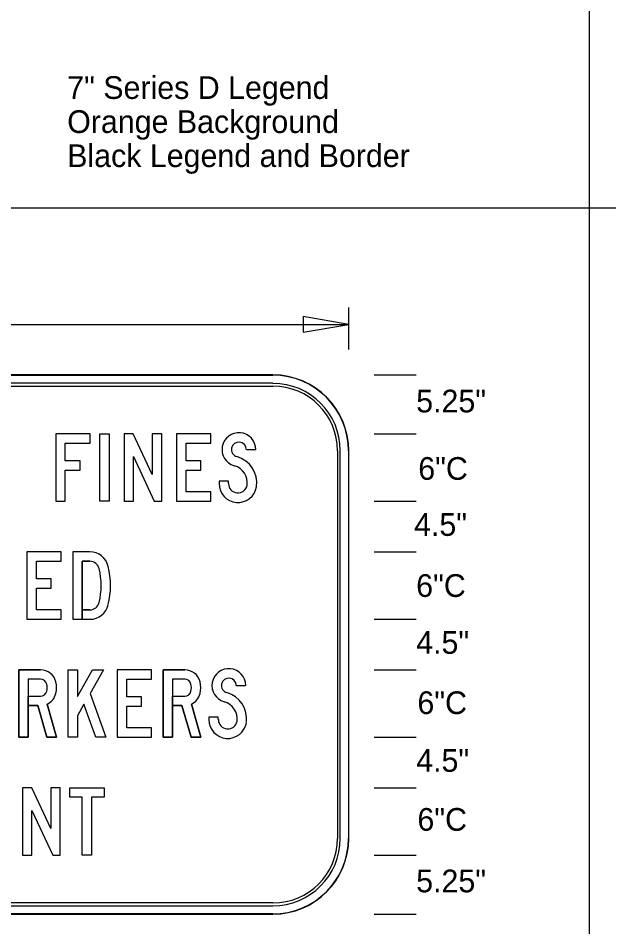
# Model space of a CAD drawing. Extents: x 0 to 770, y 0 to 495.
# Drawn here: x 296.9 to 388, y 219.2 to 359.3 of the extents above; entities that cross this region are included whole.
import ezdxf

# ---------------------------------------------------------------- set-up
doc = ezdxf.new("R2010")
doc.units = 0
for name, color, linetype in [('Dimension', 7, 'Continuous'), ('GSBWFill', 7, 'Continuous'), ('GSColorFill', 7, 'Continuous'), ('GSDims', 7, 'Continuous'), ('GSOutline', 7, 'Continuous'), ('SheetLines_dp', 7, 'Continuous'), ('TextStructures', 7, 'Continuous')]:
    doc.layers.add(name, color=color, linetype=linetype)

msp = doc.modelspace()

# ---------------------------------------------------------------- linework, layer by layer
at = {"layer": 'Dimension'}
msp.add_lwpolyline([(347.88, 312.06), (340.87, 313.25), (340.87, 310.87)], close=True, dxfattribs=at)
at = {"layer": 'GSBWFill'}
for p, q in [((336.19, 304.27), (234.87, 304.27)), ((336.19, 302.97), (234.87, 302.97)), ((234.87, 302.53), (336.19, 302.53)), ((332.09, 292.76), (333.54, 292.76)), ((346.15, 292.57), (346.15, 232.82)), ((346.58, 232.82), (346.58, 292.57)), ((347.88, 232.82), (347.88, 292.57)), ((329.33, 287.51), (329.33, 287.9)), ((307.97, 268.05), (306.78, 268.05)), ((330.53, 256.38), (331.98, 256.38)), ((300.35, 254.75), (300.35, 254.75)), ((322.59, 254.75), (322.59, 254.75)), ((327.77, 251.13), (327.77, 251.52)), ((336.19, 222.86), (234.87, 222.86)), ((234.87, 222.43), (336.19, 222.43)), ((234.87, 221.13), (336.19, 221.13))]:
    msp.add_line(p, q, dxfattribs=at)
for points in [[(304.18, 289.56), (306.46, 289.56), (306.46, 291.02), (304.18, 291.02), (304.18, 293.72), (308.03, 293.72), (308.03, 295.17), (302.73, 295.17), (302.73, 284.78), (304.18, 284.78)], [(309.48, 295.17), (310.94, 295.17), (310.94, 284.78), (309.48, 284.78)], [(317.9, 284.78), (319.04, 284.78), (319.04, 295.17), (317.59, 295.17), (317.59, 288.89), (314.66, 295.17), (313.23, 295.17), (313.23, 284.78), (314.68, 284.78), (314.68, 291.69)], [(322.79, 286.23), (322.79, 289.56), (325.06, 289.56), (325.06, 291.02), (322.79, 291.02), (322.79, 293.72), (326.63, 293.72), (326.63, 295.17), (321.33, 295.17), (321.33, 284.78), (326.63, 284.78), (326.63, 286.23)], [(299.72, 268.05), (299.72, 271.37), (301.99, 271.37), (301.99, 272.83), (299.72, 272.83), (299.72, 275.53), (303.56, 275.53), (303.56, 276.99), (298.26, 276.99), (298.26, 266.59), (303.56, 266.59), (303.56, 268.05)], [(307.05, 253.49), (306.05, 251.73), (306.05, 248.41), (304.6, 248.41), (304.6, 258.8), (306.05, 258.8), (306.05, 254.69), (308.38, 258.8), (310.06, 258.8), (308, 255.16), (310.42, 248.41), (308.87, 248.41)], [(313.64, 249.86), (313.64, 253.19), (315.92, 253.19), (315.92, 254.64), (313.64, 254.64), (313.64, 257.34), (317.49, 257.34), (317.49, 258.8), (312.19, 258.8), (312.19, 248.41), (317.49, 248.41), (317.49, 249.86)], [(302.26, 230.22), (303.4, 230.22), (303.4, 240.61), (301.95, 240.61), (301.95, 234.33), (299.02, 240.61), (297.58, 240.61), (297.58, 230.22), (299.04, 230.22), (299.04, 237.13)], [(306.78, 239.16), (304.86, 239.16), (304.86, 240.61), (310.16, 240.61), (310.16, 239.16), (308.24, 239.16), (308.24, 230.22), (306.78, 230.22)]]:
    msp.add_lwpolyline(points, close=True, dxfattribs=at)
for points in [[(329.33, 287.9), (327.88, 287.9), (327.88, 287.51)], [(307.97, 276.99), (305.33, 276.99), (305.33, 266.59), (306.78, 266.59), (306.78, 275.53), (307.97, 275.53)], [(306.78, 268.05), (306.78, 266.59), (307.97, 266.59)], [(300.35, 257.34), (298.47, 257.34), (298.47, 248.41), (297.01, 248.41), (297.01, 258.8), (300.35, 258.8)], [(322.59, 257.34), (320.71, 257.34), (320.71, 248.41), (319.25, 248.41), (319.25, 258.8), (322.59, 258.8)], [(301.38, 253.52), (302.83, 248.41), (301.32, 248.41), (299.93, 253.29), (298.47, 253.29), (298.47, 254.75), (300.35, 254.75)], [(323.62, 253.52), (325.07, 248.41), (323.56, 248.41), (322.17, 253.29), (320.71, 253.29), (320.71, 254.75), (322.59, 254.75)], [(327.77, 251.52), (326.32, 251.52), (326.32, 251.13)]]:
    msp.add_lwpolyline(points, dxfattribs=at)
for centre, radius, start, end in [((336.19, 292.57), 11.69, 0, 90), ((336.19, 292.57), 10.39, 0, 90), ((336.19, 292.57), 9.96, 0, 90), ((330.94, 292.76), 2.6, 0, 254.2259), ((330.94, 292.76), 1.14, 0, 254.2259), ((329.49, 287.61), 4.21, 352.1298, 74.2259), ((329.49, 287.61), 2.75, 352.5804, 74.2259), ((330.79, 287.51), 2.91, 180, 350.5313), ((330.79, 287.51), 1.45, 180, 349.7857), ((307.97, 274.08), 2.91, 13.109, 90), ((307.97, 274.08), 1.45, 13.109, 90), ((298.16, 271.79), 12.99, 346.891, 13.109), ((298.16, 271.79), 11.54, 346.891, 13.109), ((307.97, 269.5), 1.45, 270, 346.891), ((307.97, 269.5), 2.91, 270, 346.891), ((300.35, 256.36), 2.44, 13.8865, 90), ((322.59, 256.36), 2.44, 13.8865, 90), ((329.39, 256.38), 2.6, 0, 254.2259), ((300.35, 256.36), 0.987, 13.8865, 90), ((299.09, 256.04), 2.29, 346.1135, 13.8865), ((299.09, 256.04), 3.74, 346.1135, 13.8865), ((322.59, 256.36), 0.987, 13.8865, 90), ((321.33, 256.04), 2.29, 346.1135, 13.8865), ((321.33, 256.04), 3.74, 346.1135, 13.8865), ((329.39, 256.38), 1.14, 0, 254.2259), ((300.35, 255.73), 0.987, 270, 346.1135), ((300.35, 255.73), 2.44, 294.8221, 346.1135), ((322.59, 255.73), 0.987, 270, 346.1135), ((322.59, 255.73), 2.44, 294.8221, 346.1135), ((327.93, 251.23), 4.21, 352.1298, 74.2259), ((327.93, 251.23), 2.75, 352.5804, 74.2259), ((329.23, 251.13), 2.91, 180, 350.5313), ((329.23, 251.13), 1.45, 180, 349.7857), ((336.19, 232.82), 10.39, 270, 0), ((336.19, 232.82), 9.96, 270, 0), ((336.19, 232.82), 11.69, 270, 0)]:
    msp.add_arc(centre, radius, start, end, dxfattribs=at)
at = {"layer": 'GSColorFill'}
for p, q in [((336.19, 304.27), (234.87, 304.27)), ((234.87, 304.22), (336.19, 304.22)), ((336.19, 302.97), (234.87, 302.97)), ((234.87, 302.53), (336.19, 302.53)), ((332.09, 292.76), (333.54, 292.76)), ((346.15, 292.57), (346.15, 232.82)), ((346.58, 232.82), (346.58, 292.57)), ((347.84, 292.57), (347.84, 232.82)), ((347.88, 232.82), (347.88, 292.57)), ((329.33, 287.51), (329.33, 287.9)), ((307.97, 268.05), (306.78, 268.05)), ((330.53, 256.38), (331.98, 256.38)), ((300.35, 254.75), (300.35, 254.75)), ((322.59, 254.75), (322.59, 254.75)), ((327.77, 251.13), (327.77, 251.52)), ((336.19, 222.86), (234.87, 222.86)), ((234.87, 222.43), (336.19, 222.43)), ((336.19, 221.17), (234.87, 221.17)), ((234.87, 221.13), (336.19, 221.13))]:
    msp.add_line(p, q, dxfattribs=at)
for points in [[(304.18, 289.56), (306.46, 289.56), (306.46, 291.02), (304.18, 291.02), (304.18, 293.72), (308.03, 293.72), (308.03, 295.17), (302.73, 295.17), (302.73, 284.78), (304.18, 284.78)], [(309.48, 295.17), (310.94, 295.17), (310.94, 284.78), (309.48, 284.78)], [(317.9, 284.78), (319.04, 284.78), (319.04, 295.17), (317.59, 295.17), (317.59, 288.89), (314.66, 295.17), (313.23, 295.17), (313.23, 284.78), (314.68, 284.78), (314.68, 291.69)], [(322.79, 286.23), (322.79, 289.56), (325.06, 289.56), (325.06, 291.02), (322.79, 291.02), (322.79, 293.72), (326.63, 293.72), (326.63, 295.17), (321.33, 295.17), (321.33, 284.78), (326.63, 284.78), (326.63, 286.23)], [(299.72, 268.05), (299.72, 271.37), (301.99, 271.37), (301.99, 272.83), (299.72, 272.83), (299.72, 275.53), (303.56, 275.53), (303.56, 276.99), (298.26, 276.99), (298.26, 266.59), (303.56, 266.59), (303.56, 268.05)], [(307.05, 253.49), (306.05, 251.73), (306.05, 248.41), (304.6, 248.41), (304.6, 258.8), (306.05, 258.8), (306.05, 254.69), (308.38, 258.8), (310.06, 258.8), (308, 255.16), (310.42, 248.41), (308.87, 248.41)], [(313.64, 249.86), (313.64, 253.19), (315.92, 253.19), (315.92, 254.64), (313.64, 254.64), (313.64, 257.34), (317.49, 257.34), (317.49, 258.8), (312.19, 258.8), (312.19, 248.41), (317.49, 248.41), (317.49, 249.86)], [(302.26, 230.22), (303.4, 230.22), (303.4, 240.61), (301.95, 240.61), (301.95, 234.33), (299.02, 240.61), (297.58, 240.61), (297.58, 230.22), (299.04, 230.22), (299.04, 237.13)], [(306.78, 239.16), (304.86, 239.16), (304.86, 240.61), (310.16, 240.61), (310.16, 239.16), (308.24, 239.16), (308.24, 230.22), (306.78, 230.22)]]:
    msp.add_lwpolyline(points, close=True, dxfattribs=at)
for points in [[(329.33, 287.9), (327.88, 287.9), (327.88, 287.51)], [(307.97, 276.99), (305.33, 276.99), (305.33, 266.59), (306.78, 266.59), (306.78, 275.53), (307.97, 275.53)], [(306.78, 268.05), (306.78, 266.59), (307.97, 266.59)], [(300.35, 257.34), (298.47, 257.34), (298.47, 248.41), (297.01, 248.41), (297.01, 258.8), (300.35, 258.8)], [(322.59, 257.34), (320.71, 257.34), (320.71, 248.41), (319.25, 248.41), (319.25, 258.8), (322.59, 258.8)], [(301.38, 253.52), (302.83, 248.41), (301.32, 248.41), (299.93, 253.29), (298.47, 253.29), (298.47, 254.75), (300.35, 254.75)], [(323.62, 253.52), (325.07, 248.41), (323.56, 248.41), (322.17, 253.29), (320.71, 253.29), (320.71, 254.75), (322.59, 254.75)], [(327.77, 251.52), (326.32, 251.52), (326.32, 251.13)]]:
    msp.add_lwpolyline(points, dxfattribs=at)
for centre, radius, start, end in [((336.19, 292.57), 11.69, 0, 90), ((336.19, 292.57), 11.65, 0, 90), ((336.19, 292.57), 10.39, 0, 90), ((336.19, 292.57), 9.96, 0, 90), ((330.94, 292.76), 2.6, 0, 254.2259), ((330.94, 292.76), 1.14, 0, 254.2259), ((329.49, 287.61), 4.21, 352.1298, 74.2259), ((329.49, 287.61), 2.75, 352.5804, 74.2259), ((330.79, 287.51), 2.91, 180, 350.5313), ((330.79, 287.51), 1.45, 180, 349.7857), ((307.97, 274.08), 2.91, 13.109, 90), ((307.97, 274.08), 1.45, 13.109, 90), ((298.16, 271.79), 12.99, 346.891, 13.109), ((298.16, 271.79), 11.54, 346.891, 13.109), ((307.97, 269.5), 1.45, 270, 346.891), ((307.97, 269.5), 2.91, 270, 346.891), ((300.35, 256.36), 2.44, 13.8865, 90), ((322.59, 256.36), 2.44, 13.8865, 90), ((329.39, 256.38), 2.6, 0, 254.2259), ((300.35, 256.36), 0.987, 13.8865, 90), ((299.09, 256.04), 2.29, 346.1135, 13.8865), ((299.09, 256.04), 3.74, 346.1135, 13.8865), ((322.59, 256.36), 0.987, 13.8865, 90), ((321.33, 256.04), 2.29, 346.1135, 13.8865), ((321.33, 256.04), 3.74, 346.1135, 13.8865), ((329.39, 256.38), 1.14, 0, 254.2259), ((300.35, 255.73), 0.987, 270, 346.1135), ((300.35, 255.73), 2.44, 294.8221, 346.1135), ((322.59, 255.73), 0.987, 270, 346.1135), ((322.59, 255.73), 2.44, 294.8221, 346.1135), ((327.93, 251.23), 4.21, 352.1298, 74.2259), ((327.93, 251.23), 2.75, 352.5804, 74.2259), ((329.23, 251.13), 2.91, 180, 350.5313), ((329.23, 251.13), 1.45, 180, 349.7857), ((336.19, 232.82), 10.39, 270, 0), ((336.19, 232.82), 9.96, 270, 0), ((336.19, 232.82), 11.69, 270, 0), ((336.19, 232.82), 11.65, 270, 0)]:
    msp.add_arc(centre, radius, start, end, dxfattribs=at)
at = {"layer": 'GSDims'}
for p, q in [((347.88, 308.16), (347.88, 314.66)), ((223.18, 312.06), (347.88, 312.06)), ((351.78, 304.27), (358.28, 304.27)), ((351.78, 295.17), (358.28, 295.17)), ((351.78, 295.17), (358.28, 295.17)), ((351.78, 284.78), (358.28, 284.78)), ((351.78, 284.78), (358.28, 284.78)), ((351.78, 276.99), (358.28, 276.99)), ((351.78, 276.99), (358.28, 276.99)), ((351.78, 266.59), (358.28, 266.59)), ((351.78, 266.59), (358.28, 266.59)), ((351.78, 258.8), (358.28, 258.8)), ((351.78, 258.8), (358.28, 258.8)), ((351.78, 248.41), (358.28, 248.41)), ((351.78, 248.41), (358.28, 248.41)), ((351.78, 240.61), (358.28, 240.61)), ((351.78, 240.61), (358.28, 240.61)), ((351.78, 230.22), (358.28, 230.22)), ((351.78, 230.22), (358.28, 230.22)), ((351.78, 221.13), (358.28, 221.13))]:
    msp.add_line(p, q, dxfattribs=at)
at = {"layer": 'GSOutline'}
for p, q in [((332.09, 292.76), (333.54, 292.76)), ((329.33, 287.51), (329.33, 287.9)), ((306.78, 268.05), (307.97, 268.05)), ((307.97, 266.59), (307.97, 266.59)), ((300.35, 258.8), (297.01, 258.8)), ((322.59, 258.8), (319.25, 258.8)), ((300.35, 257.34), (300.35, 257.34)), ((322.59, 257.34), (322.59, 257.34)), ((330.53, 256.38), (331.98, 256.38)), ((327.77, 251.13), (327.77, 251.52))]:
    msp.add_line(p, q, dxfattribs=at)
for points in [[(304.18, 289.56), (306.46, 289.56), (306.46, 291.02), (304.18, 291.02), (304.18, 293.72), (308.03, 293.72), (308.03, 295.17), (302.73, 295.17), (302.73, 284.78), (304.18, 284.78)], [(309.48, 295.17), (310.94, 295.17), (310.94, 284.78), (309.48, 284.78)], [(317.9, 284.78), (319.04, 284.78), (319.04, 295.17), (317.59, 295.17), (317.59, 288.89), (314.66, 295.17), (313.23, 295.17), (313.23, 284.78), (314.68, 284.78), (314.68, 291.69)], [(322.79, 286.23), (322.79, 289.56), (325.06, 289.56), (325.06, 291.02), (322.79, 291.02), (322.79, 293.72), (326.63, 293.72), (326.63, 295.17), (321.33, 295.17), (321.33, 284.78), (326.63, 284.78), (326.63, 286.23)], [(299.72, 268.05), (299.72, 271.37), (301.99, 271.37), (301.99, 272.83), (299.72, 272.83), (299.72, 275.53), (303.56, 275.53), (303.56, 276.99), (298.26, 276.99), (298.26, 266.59), (303.56, 266.59), (303.56, 268.05)], [(307.05, 253.49), (306.05, 251.73), (306.05, 248.41), (304.6, 248.41), (304.6, 258.8), (306.05, 258.8), (306.05, 254.69), (308.38, 258.8), (310.06, 258.8), (308, 255.16), (310.42, 248.41), (308.87, 248.41)], [(313.64, 249.86), (313.64, 253.19), (315.92, 253.19), (315.92, 254.64), (313.64, 254.64), (313.64, 257.34), (317.49, 257.34), (317.49, 258.8), (312.19, 258.8), (312.19, 248.41), (317.49, 248.41), (317.49, 249.86)], [(302.26, 230.22), (303.4, 230.22), (303.4, 240.61), (301.95, 240.61), (301.95, 234.33), (299.02, 240.61), (297.58, 240.61), (297.58, 230.22), (299.04, 230.22), (299.04, 237.13)], [(306.78, 239.16), (304.86, 239.16), (304.86, 240.61), (310.16, 240.61), (310.16, 239.16), (308.24, 239.16), (308.24, 230.22), (306.78, 230.22)]]:
    msp.add_lwpolyline(points, close=True, dxfattribs=at)
for points in [[(329.33, 287.9), (327.88, 287.9), (327.88, 287.51)], [(307.97, 276.99), (305.33, 276.99), (305.33, 266.59), (307.97, 266.59)], [(307.97, 275.53), (306.78, 275.53), (306.78, 268.05)], [(297.01, 258.8), (297.01, 248.41), (298.47, 248.41), (298.47, 253.29), (299.93, 253.29), (301.32, 248.41), (302.83, 248.41), (301.38, 253.52)], [(319.25, 258.8), (319.25, 248.41), (320.71, 248.41), (320.71, 253.29), (322.17, 253.29), (323.56, 248.41), (325.07, 248.41), (323.62, 253.52)], [(300.35, 257.34), (298.47, 257.34), (298.47, 254.75), (300.35, 254.75)], [(322.59, 257.34), (320.71, 257.34), (320.71, 254.75), (322.59, 254.75)], [(327.77, 251.52), (326.32, 251.52), (326.32, 251.13)]]:
    msp.add_lwpolyline(points, dxfattribs=at)
for centre, radius, start, end in [((330.94, 292.76), 2.6, 0, 254.2259), ((330.94, 292.76), 1.14, 0, 254.2259), ((329.49, 287.61), 4.21, 352.1298, 74.2259), ((329.49, 287.61), 2.75, 352.5804, 74.2259), ((330.79, 287.51), 2.91, 180, 350.5313), ((330.79, 287.51), 1.45, 180, 349.7857), ((307.97, 274.08), 2.91, 13.109, 90), ((307.97, 274.08), 1.45, 13.109, 90), ((298.16, 271.79), 12.99, 346.891, 13.109), ((298.16, 271.79), 11.54, 346.891, 13.109), ((307.97, 269.5), 1.45, 270, 346.891), ((307.97, 269.5), 2.91, 270, 346.891), ((300.35, 256.36), 2.44, 13.8865, 90), ((322.59, 256.36), 2.44, 13.8865, 90), ((329.39, 256.38), 2.6, 0, 254.2259), ((300.35, 256.36), 0.987, 13.8865, 90), ((299.09, 256.04), 2.29, 346.1135, 13.8865), ((299.09, 256.04), 3.74, 346.1135, 13.8865), ((322.59, 256.36), 0.987, 13.8865, 90), ((321.33, 256.04), 2.29, 346.1135, 13.8865), ((321.33, 256.04), 3.74, 346.1135, 13.8865), ((329.39, 256.38), 1.14, 0, 254.2259), ((300.35, 255.73), 0.987, 270, 346.1135), ((300.35, 255.73), 2.44, 294.8221, 346.1135), ((322.59, 255.73), 0.987, 270, 346.1135), ((322.59, 255.73), 2.44, 294.8221, 346.1135), ((327.93, 251.23), 4.21, 352.1298, 74.2259), ((327.93, 251.23), 2.75, 352.5804, 74.2259), ((329.23, 251.13), 2.91, 180, 350.5313), ((329.23, 251.13), 1.45, 180, 349.7857)]:
    msp.add_arc(centre, radius, start, end, dxfattribs=at)
at = {"layer": 'SheetLines_dp'}
for p, q in [((385, 0), (385, 495)), ((0, 330), (770, 330))]:
    msp.add_line(p, q, dxfattribs=at)

# ---------------------------------------------------------------- texts
at = {"layer": 'TextStructures'}
for s, p in [('7" Series D Legend', (304.47, 346.81)), ('Orange Background', (304.47, 341.56)), ('Black Legend and Border  ', (304.47, 336.31)), ('5.25"', (358.28, 298.48)), ('6"C', (358.6, 288.09)), ('4.5"', (357.95, 279.45)), ('6"C', (358.28, 270.04)), ('4.5"', (358.28, 261.27)), ('6"C', (358.47, 251.98)), ('4.5"', (358.28, 243.08)), ('6"C', (358.47, 233.99)), ('5.25"', (358.28, 224.5))]:
    msp.add_text(s, height=3.5, dxfattribs=at).set_placement(p)

doc.saveas('drawing.dxf')
